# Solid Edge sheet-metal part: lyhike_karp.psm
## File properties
Author: Mac
Template: Normal.psm
Last saved by: Mac
Revision: 3
Application: Solid Edge
Material: Aluminum, 1060
Face Style: Aluminum
Fill Style: ANSI38(Aluminum)
Virtual Style: Brushed aluminum pattern
Coef. of Thermal Exp: 2.3e-05
Thermal Conductivity: 221.0
Specific Heat: 920.0
Modulus of Elasticity: 68947570000.0
Poission's Ratio: 0.33
Yield Stress: 27579028.0
Ultimate Stress: 68947570.0
Elongation: 0.0
Density: 2712,000 kg/m^3
Accuracy: 0,990
Material Thickness: 0,06 mm
Bend Radius: 1,00 mm
Relief Width: 1,00 mm
Relief Length: 0,00 mm
Neutral Factor: 0,330
Minimum Arc Length: 0,10 mm
Deviational Tolerance: 0,10 mm
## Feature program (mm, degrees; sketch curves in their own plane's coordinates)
base contour flange "ContourFlange_1"
sheet metal cutout "unnamed SheetMetalCutout 1"
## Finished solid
Body 1: solid body, 22 faces, 44 edges, 24 vertices.
  Faces by surface: plane 14, cylinder 4, spline 4
  Edges by curve: line 36, ellipse 8
Bounding box of the edges (mm; curved faces can reach further): 1.400 x 27.680 x 0.800, from (-0.7, 0.06, 0) to (0.7, 27.74, 0.8).
Cylindrical faces by radius (mm): R0.002 x2, R0.062 x2
Planar faces by outward normal: +x 2, +y 2, +z 3, -x 2, -y 2, -z 1, oblique 2
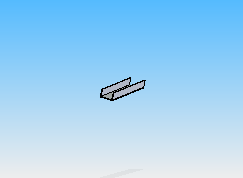
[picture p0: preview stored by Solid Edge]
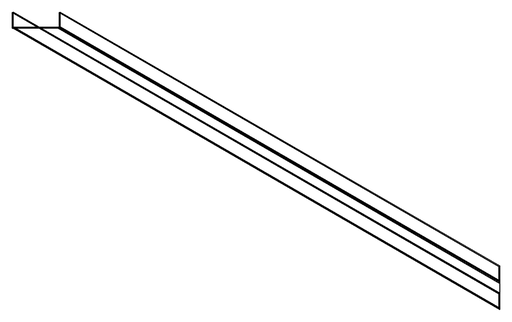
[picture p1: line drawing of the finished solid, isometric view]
